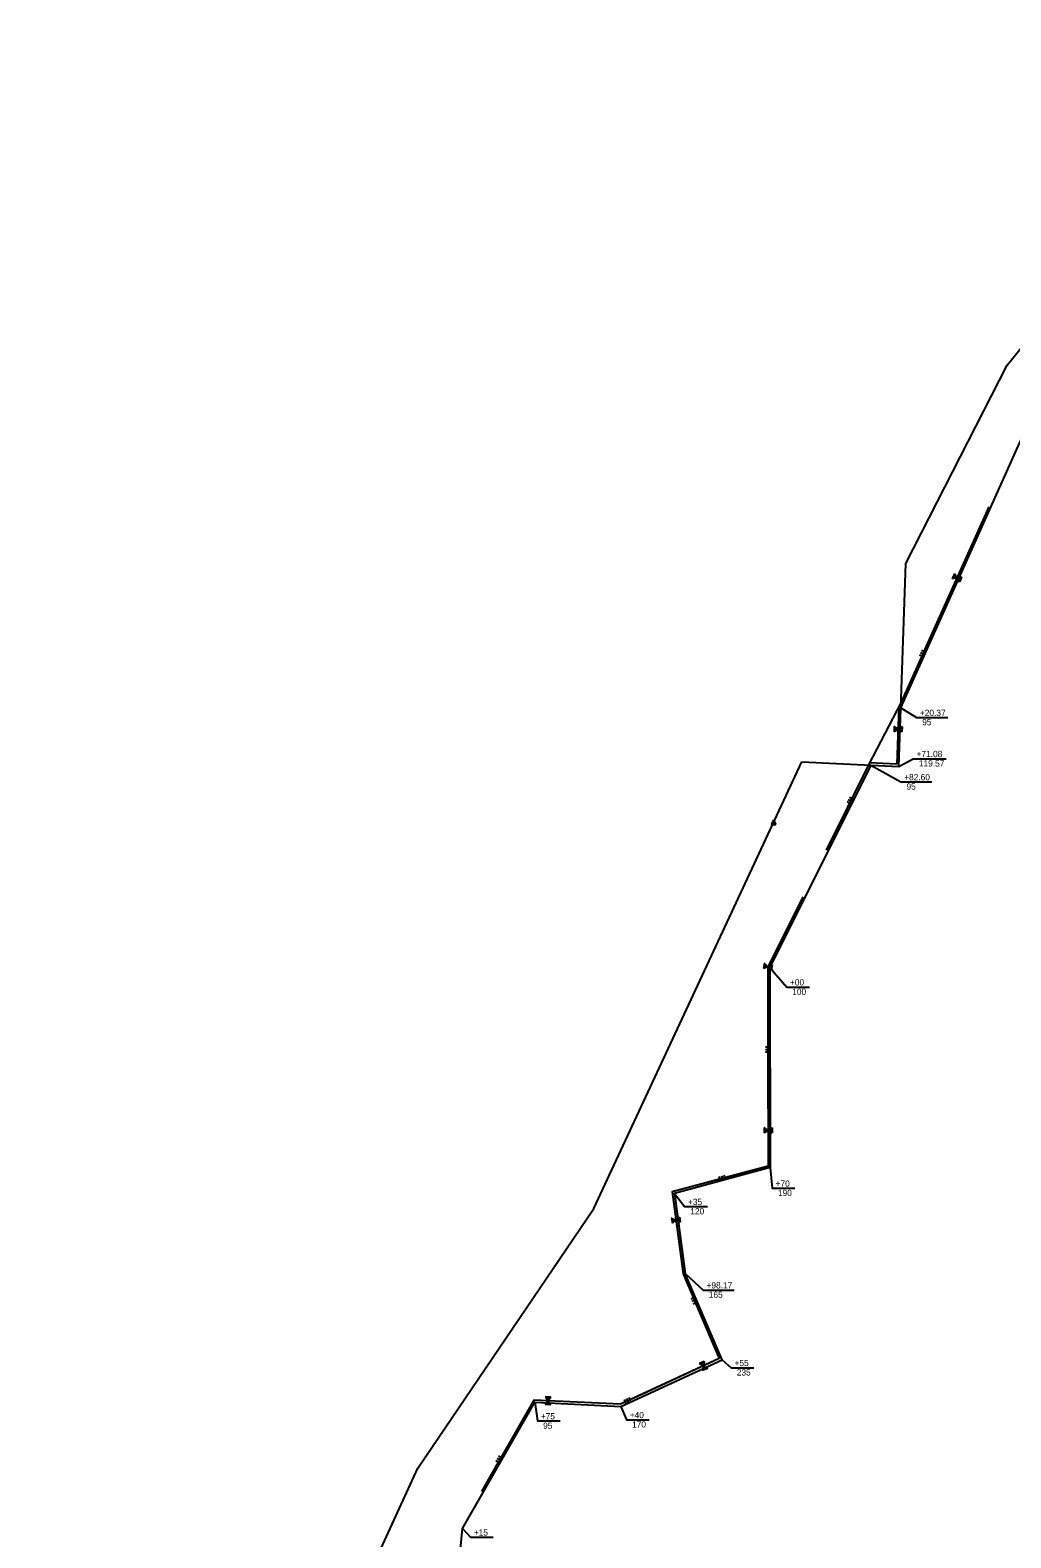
# Model space of a CAD drawing. Extents: x 979729 to 993523, y 1834148 to 1845433.
# Drawn here: x 980541 to 981483, y 1840365 to 1841814 of the extents above; entities that cross this region are included whole.
import ezdxf

# ---------------------------------------------------------------- set-up
doc = ezdxf.new("R2010")
doc.units = 0
for name, color, linetype in [('42', 7, 'Continuous'), ('51', 7, 'Continuous'), ('R_Draft', 7, 'Continuous'), ('S_EXIST_ROW', 7, 'Continuous')]:
    doc.layers.add(name, color=color, linetype=linetype)

msp = doc.modelspace()

# ---------------------------------------------------------------- linework, layer by layer
at = {"layer": '42'}
for p, q in [((981462.3, 1841356.2), (981377.9, 1841168.2)), ((981431.6, 1841287.8), (981427.1, 1841287)), ((981431.5, 1841287.9), (981427.2, 1841287.1)), ((981431.3, 1841288.1), (981427.3, 1841287.4)), ((981431.2, 1841288.3), (981427.4, 1841287.7)), ((981431.1, 1841288.5), (981427.6, 1841287.9)), ((981430.9, 1841288.8), (981427.7, 1841288.2)), ((981430.8, 1841289), (981427.8, 1841288.5)), ((981430.7, 1841289.2), (981427.9, 1841288.8)), ((981430.5, 1841289.5), (981428, 1841289)), ((981430.3, 1841289.7), (981428.2, 1841289.3)), ((981430.1, 1841290.1), (981428.4, 1841289.9)), ((981430, 1841290.4), (981428.5, 1841290.1)), ((981430.1, 1841289.9), (981428.5, 1841289.6)), ((981429.8, 1841290.6), (981428.7, 1841290.4)), ((981429.6, 1841290.8), (981428.8, 1841290.7)), ((981429.5, 1841291.1), (981428.9, 1841291)), ((981429.3, 1841291.3), (981429, 1841291.2)), ((981429.2, 1841291.6), (981431.6, 1841287.8)), ((981429.2, 1841291.5), (981429.2, 1841291.5)), ((981436, 1841288.5), (981431.6, 1841287.8)), ((981431.6, 1841287.8), (981434, 1841284)), ((981431.7, 1841287.8), (981434, 1841284.1)), ((981432, 1841287.8), (981434.2, 1841284.3)), ((981432.2, 1841287.9), (981434.3, 1841284.6)), ((981432.5, 1841287.9), (981434.4, 1841284.9)), ((981432.8, 1841288), (981434.5, 1841285.2)), ((981433.1, 1841288), (981434.6, 1841285.4)), ((981433.3, 1841288), (981434.8, 1841285.7)), ((981433.6, 1841288.1), (981434.9, 1841286)), ((981433.8, 1841288.1), (981435, 1841286.2)), ((981434.1, 1841288.1), (981435, 1841286.7)), ((981434.4, 1841288.2), (981435.3, 1841286.8)), ((981434.6, 1841288.3), (981435.4, 1841287.1)), ((981434.9, 1841288.3), (981435.5, 1841287.3)), ((981435.2, 1841288.3), (981435.6, 1841287.6)), ((981435.4, 1841288.4), (981435.8, 1841287.9)), ((981435.7, 1841288.4), (981435.9, 1841288.2)), ((981436, 1841288.5), (981436, 1841288.4)), ((981400.1, 1841211.5), (981395.5, 1841213.5)), ((981401.1, 1841213.8), (981396.6, 1841215.8)), ((981402.1, 1841216.1), (981397.6, 1841218.1)), ((981377.9, 1841168.2), (981346.6, 1841108)), ((981375, 1841142.3), (981371.2, 1841140)), ((981375.1, 1841142.3), (981371.2, 1841139.9)), ((981372.8, 1841143.9), (981371.3, 1841143)), ((981373.2, 1841143.6), (981371.3, 1841142.4)), ((981373.4, 1841143.4), (981371.3, 1841142.1)), ((981373.7, 1841143.3), (981371.3, 1841141.8)), ((981373.8, 1841143.1), (981371.3, 1841141.5)), ((981374.1, 1841143), (981371.3, 1841141.2)), ((981374.3, 1841142.8), (981371.3, 1841140.9)), ((981374.5, 1841142.7), (981371.3, 1841140.6)), ((981374.7, 1841142.5), (981371.3, 1841140.3)), ((981371.4, 1841144.9), (981375.1, 1841142.3)), ((981371.7, 1841144.7), (981371.4, 1841144.5)), ((981371.9, 1841144.6), (981371.4, 1841144.2)), ((981372.1, 1841144.4), (981371.4, 1841143.9)), ((981372.3, 1841144.2), (981371.4, 1841143.6)), ((981372.6, 1841144.1), (981371.4, 1841143.3)), ((981372.9, 1841143.7), (981371.5, 1841142.8)), ((981378.9, 1841144.7), (981375.1, 1841142.3)), ((981375.1, 1841142.3), (981378.7, 1841139.7)), ((981375.2, 1841142.3), (981378.7, 1841139.8)), ((981375.4, 1841142.5), (981378.7, 1841140.1)), ((981375.6, 1841142.6), (981378.8, 1841140.4)), ((981375.9, 1841142.8), (981378.8, 1841140.7)), ((981376.1, 1841142.9), (981378.8, 1841141)), ((981376.4, 1841143), (981378.8, 1841141.3)), ((981376.5, 1841143.2), (981378.8, 1841141.6)), ((981376.8, 1841143.3), (981378.8, 1841141.9)), ((981377, 1841143.5), (981378.8, 1841142.2)), ((981377.3, 1841143.6), (981378.7, 1841142.6)), ((981377.5, 1841143.8), (981378.8, 1841142.8)), ((981377.7, 1841143.9), (981378.8, 1841143.1)), ((981377.9, 1841144), (981378.9, 1841143.4)), ((981378.2, 1841144.2), (981378.9, 1841143.7)), ((981378.4, 1841144.3), (981378.9, 1841144)), ((981378.6, 1841144.5), (981378.9, 1841144.3)), ((981378.8, 1841144.6), (981378.9, 1841144.6)), ((981346.6, 1841108), (981305.8, 1841026.1)), ((981330.5, 1841070.1), (981326, 1841072.4)), ((981331.6, 1841072.4), (981327.2, 1841074.6)), ((981332.7, 1841074.6), (981328.3, 1841076.8)), ((981283.5, 1840981.3), (981249.9, 1840913.7)), ((981249.8, 1840914), (981245.7, 1840912.4)), ((981249.9, 1840913.9), (981245.7, 1840912.3)), ((981249.4, 1840914.4), (981245.8, 1840913)), ((981249.6, 1840914.1), (981245.8, 1840912.7)), ((981249.2, 1840914.5), (981245.9, 1840913.3)), ((981248.8, 1840914.9), (981246, 1840913.9)), ((981249.1, 1840914.8), (981246, 1840913.6)), ((981248.7, 1840915.1), (981246.1, 1840914.2)), ((981248.3, 1840915.5), (981246.2, 1840914.8)), ((981248.5, 1840915.3), (981246.2, 1840914.5)), ((981247.8, 1840916.1), (981246.4, 1840915.6)), ((981248, 1840915.9), (981246.4, 1840915.4)), ((981247.6, 1840916.3), (981246.5, 1840915.9)), ((981248.1, 1840915.7), (981246.5, 1840915.1)), ((981247.4, 1840916.5), (981246.6, 1840916.2)), ((981247, 1840916.9), (981246.7, 1840916.8)), ((981247.2, 1840916.7), (981246.7, 1840916.5)), ((981246.8, 1840917.2), (981249.9, 1840913.9)), ((981246.9, 1840917.1), (981246.8, 1840917.1)), ((981254.1, 1840915.5), (981249.9, 1840913.9)), ((981249.9, 1840913.9), (981253, 1840910.6)), ((981249.9, 1840913.7), (981250.2, 1840722.4)), ((981250, 1840913.9), (981253, 1840910.7)), ((981250.3, 1840914), (981253, 1840911)), ((981250.5, 1840914.1), (981253.1, 1840911.3)), ((981250.8, 1840914.2), (981253.2, 1840911.6)), ((981251, 1840914.3), (981253.3, 1840911.9)), ((981251.3, 1840914.3), (981253.3, 1840912.2)), ((981251.5, 1840914.5), (981253.4, 1840912.4)), ((981251.8, 1840914.5), (981253.5, 1840912.7)), ((981252, 1840914.6), (981253.5, 1840913)), ((981252.3, 1840914.7), (981253.5, 1840913.4)), ((981252.5, 1840914.9), (981253.7, 1840913.6)), ((981252.8, 1840915), (981253.7, 1840913.9)), ((981253, 1840915), (981253.8, 1840914.2)), ((981253.3, 1840915.1), (981253.9, 1840914.5)), ((981253.5, 1840915.2), (981254, 1840914.8)), ((981253.8, 1840915.3), (981254, 1840915.1)), ((981254, 1840915.4), (981254.1, 1840915.4)), ((981252.5, 1840836.7), (981247.5, 1840836.7)), ((981252.5, 1840834.2), (981247.5, 1840834.2)), ((981252.5, 1840831.7), (981247.5, 1840831.7)), ((981246.5, 1840759.2), (981246.4, 1840759.1)), ((981246.4, 1840759.2), (981250.2, 1840756.7)), ((981246.7, 1840759), (981246.4, 1840758.8)), ((981246.9, 1840758.9), (981246.4, 1840758.5)), ((981247.1, 1840758.7), (981246.4, 1840758.2)), ((981247.4, 1840758.6), (981246.4, 1840757.9)), ((981247.6, 1840758.4), (981246.4, 1840757.6)), ((981247.8, 1840758.3), (981246.4, 1840757.3)), ((981248.2, 1840758), (981246.4, 1840756.7)), ((981248.5, 1840757.8), (981246.4, 1840756.4)), ((981248.7, 1840757.7), (981246.4, 1840756.1)), ((981248.9, 1840757.5), (981246.4, 1840755.8)), ((981249.2, 1840757.4), (981246.4, 1840755.5)), ((981249.4, 1840757.2), (981246.4, 1840755.2)), ((981249.6, 1840757.1), (981246.4, 1840754.9)), ((981249.8, 1840756.9), (981246.4, 1840754.6)), ((981250.1, 1840756.8), (981246.4, 1840754.3)), ((981250.2, 1840756.7), (981246.4, 1840754.2)), ((981248, 1840758.1), (981246.6, 1840757.1)), ((981253.9, 1840759.2), (981250.2, 1840756.7)), ((981250.2, 1840756.7), (981253.9, 1840754.2)), ((981250.3, 1840756.8), (981253.9, 1840754.3)), ((981250.5, 1840756.9), (981253.9, 1840754.6)), ((981250.7, 1840757.1), (981253.9, 1840755)), ((981251, 1840757.2), (981253.9, 1840755.3)), ((981251.2, 1840757.4), (981253.9, 1840755.6)), ((981251.4, 1840757.5), (981253.9, 1840755.9)), ((981251.6, 1840757.7), (981253.9, 1840756.2)), ((981251.9, 1840757.8), (981253.9, 1840756.5)), ((981252.1, 1840758), (981253.9, 1840756.8)), ((981252.4, 1840758.1), (981253.8, 1840757.1)), ((981252.5, 1840758.3), (981253.9, 1840757.4)), ((981252.7, 1840758.4), (981253.9, 1840757.7)), ((981253, 1840758.6), (981253.9, 1840758)), ((981253.2, 1840758.7), (981253.9, 1840758.3)), ((981253.4, 1840758.9), (981253.9, 1840758.6)), ((981253.7, 1840759), (981253.9, 1840758.9)), ((981253.9, 1840759.2), (981253.9, 1840759.2)), ((981250.2, 1840722.4), (981157.8, 1840697.5)), ((981204.4, 1840707.5), (981203.1, 1840712.3)), ((981206.8, 1840708.1), (981205.5, 1840712.9)), ((981209.2, 1840708.8), (981207.9, 1840713.6)), ((981157.8, 1840697.5), (981168.4, 1840618.6)), ((981157.4, 1840672.3), (981161.5, 1840670.3)), ((981157.5, 1840672.2), (981157.4, 1840672.2)), ((981157.7, 1840672.1), (981157.5, 1840671.9)), ((981158, 1840672), (981157.5, 1840671.6)), ((981158.2, 1840671.9), (981157.5, 1840671.3)), ((981158.4, 1840671.7), (981157.6, 1840671)), ((981158.7, 1840671.6), (981157.6, 1840670.7)), ((981158.9, 1840671.5), (981157.7, 1840670.4)), ((981159.4, 1840671.3), (981157.7, 1840669.8)), ((981159.1, 1840671.3), (981157.8, 1840670.2)), ((981159.6, 1840671.1), (981157.8, 1840669.5)), ((981159.9, 1840671), (981157.8, 1840669.2)), ((981160.1, 1840670.9), (981157.9, 1840668.9)), ((981160.4, 1840670.8), (981157.9, 1840668.6)), ((981160.6, 1840670.7), (981157.9, 1840668.3)), ((981160.9, 1840670.6), (981158, 1840668)), ((981161.1, 1840670.4), (981158, 1840667.7)), ((981161.4, 1840670.3), (981158.1, 1840667.4)), ((981161.5, 1840670.3), (981158.1, 1840667.3)), ((981164.8, 1840673.3), (981161.5, 1840670.3)), ((981161.5, 1840670.3), (981165.5, 1840668.4)), ((981161.5, 1840670.3), (981165.5, 1840668.3)), ((981161.8, 1840670.5), (981165.5, 1840668.7)), ((981162, 1840670.7), (981165.4, 1840669)), ((981162.2, 1840670.9), (981165.4, 1840669.3)), ((981162.4, 1840671.1), (981165.3, 1840669.6)), ((981162.6, 1840671.2), (981165.3, 1840669.9)), ((981162.8, 1840671.4), (981165.3, 1840670.2)), ((981163, 1840671.6), (981165.2, 1840670.5)), ((981163.2, 1840671.8), (981165.2, 1840670.8)), ((981163.4, 1840671.9), (981165, 1840671.2)), ((981163.6, 1840672.1), (981165.1, 1840671.4)), ((981163.8, 1840672.3), (981165.1, 1840671.7)), ((981164, 1840672.5), (981165, 1840672)), ((981164.2, 1840672.7), (981165, 1840672.3)), ((981164.4, 1840672.9), (981164.9, 1840672.6)), ((981164.6, 1840673), (981164.9, 1840672.9)), ((981164.8, 1840673.2), (981164.9, 1840673.2)), ((981168.4, 1840618.6), (981203.2, 1840537.2)), ((981180.7, 1840596.3), (981176.1, 1840594.3)), ((981181.7, 1840594), (981177.1, 1840592)), ((981182.7, 1840591.7), (981178.1, 1840589.7)), ((981203.2, 1840537.2), (981108.3, 1840493.3)), ((981187.9, 1840530.2), (981184.1, 1840532.5)), ((981187.9, 1840530.3), (981184.2, 1840532.6)), ((981187.9, 1840530.6), (981184.4, 1840532.7)), ((981188, 1840530.8), (981184.7, 1840532.8)), ((981188, 1840531.1), (981185, 1840532.9)), ((981188.1, 1840531.3), (981185.3, 1840533.1)), ((981188.1, 1840531.6), (981185.5, 1840533.2)), ((981188.2, 1840531.9), (981185.8, 1840533.3)), ((981188.2, 1840532.2), (981186.1, 1840533.4)), ((981188.2, 1840532.4), (981186.4, 1840533.6)), ((981188.2, 1840532.7), (981186.8, 1840533.6)), ((981188.3, 1840532.9), (981186.9, 1840533.8)), ((981188.4, 1840533.2), (981187.2, 1840533.9)), ((981187.9, 1840530.2), (981187.2, 1840525.7)), ((981188, 1840530.1), (981187.3, 1840525.8)), ((981188.4, 1840533.5), (981187.4, 1840534.1)), ((981188.2, 1840529.9), (981187.6, 1840525.9)), ((981188.5, 1840533.8), (981187.7, 1840534.2)), ((981188.6, 1840534.6), (981187.9, 1840530.2)), ((981191.8, 1840527.8), (981187.9, 1840530.2)), ((981188.5, 1840529.8), (981187.9, 1840526)), ((981188.5, 1840534), (981188, 1840534.3)), ((981188.7, 1840529.7), (981188.1, 1840526.1)), ((981188.5, 1840534.3), (981188.3, 1840534.5)), ((981188.9, 1840529.5), (981188.4, 1840526.3)), ((981188.6, 1840534.5), (981188.5, 1840534.6)), ((981189.1, 1840529.3), (981188.7, 1840526.4)), ((981189.4, 1840529.2), (981189, 1840526.5)), ((981189.6, 1840529.1), (981189.2, 1840526.6)), ((981189.8, 1840528.9), (981189.5, 1840526.8)), ((981190.1, 1840528.7), (981189.8, 1840527.1)), ((981190.3, 1840528.7), (981190.1, 1840527)), ((981190.5, 1840528.6), (981190.3, 1840527.1)), ((981190.8, 1840528.4), (981190.6, 1840527.3)), ((981191, 1840528.2), (981190.9, 1840527.4)), ((981191.2, 1840528.1), (981191.1, 1840527.5)), ((981191.5, 1840528), (981191.4, 1840527.6)), ((981191.7, 1840527.8), (981191.7, 1840527.8)), ((981038.6, 1840496.7), (981036.3, 1840500.6)), ((981038.7, 1840496.8), (981036.4, 1840500.6)), ((981038.8, 1840497.1), (981036.7, 1840500.6)), ((981039, 1840497.2), (981037, 1840500.5)), ((981039.1, 1840497.5), (981037.3, 1840500.5)), ((981039.3, 1840497.7), (981037.6, 1840500.5)), ((981039.4, 1840497.9), (981037.9, 1840500.5)), ((981039.6, 1840498.1), (981038.2, 1840500.5)), ((981039.8, 1840498.4), (981038.5, 1840500.5)), ((981041.3, 1840500.3), (981038.6, 1840496.7)), ((981039.9, 1840498.6), (981038.8, 1840500.5)), ((981040.1, 1840498.8), (981039.2, 1840500.3)), ((981040.3, 1840499), (981039.4, 1840500.4)), ((981040.4, 1840499.2), (981039.7, 1840500.4)), ((981040.6, 1840499.4), (981040, 1840500.4)), ((981040.7, 1840499.7), (981040.3, 1840500.4)), ((981040.9, 1840499.9), (981040.6, 1840500.4)), ((981041.1, 1840500.1), (981040.9, 1840500.4)), ((981041.2, 1840500.3), (981041.2, 1840500.3)), ((981024.9, 1840497.4), (980974.5, 1840409.4)), ((981108.3, 1840493.3), (981024.9, 1840497.4)), ((981038.6, 1840496.7), (981035.9, 1840493.1)), ((981038.6, 1840496.6), (981036, 1840493.1)), ((981038.8, 1840496.4), (981036.3, 1840493.1)), ((981038.9, 1840496.2), (981036.6, 1840493.1)), ((981039, 1840495.9), (981036.9, 1840493)), ((981039.2, 1840495.7), (981037.2, 1840493)), ((981039.3, 1840495.4), (981037.5, 1840493)), ((981039.5, 1840495.2), (981037.8, 1840493)), ((981039.6, 1840495), (981038.1, 1840493)), ((981039.7, 1840494.7), (981038.4, 1840493)), ((981040.9, 1840492.8), (981038.6, 1840496.7)), ((981039.8, 1840494.5), (981038.8, 1840493.1)), ((981040, 1840494.3), (981039, 1840492.9)), ((981040.2, 1840494.1), (981039.3, 1840492.9)), ((981040.3, 1840493.8), (981039.6, 1840492.9)), ((981040.4, 1840493.6), (981039.9, 1840492.9)), ((981040.6, 1840493.4), (981040.2, 1840492.9)), ((981040.7, 1840493.1), (981040.5, 1840492.9)), ((981040.9, 1840492.9), (981040.8, 1840492.9)), ((981114.1, 1840493.3), (981112, 1840497.8)), ((981116.4, 1840494.3), (981114.3, 1840498.9)), ((981118.6, 1840495.4), (981116.5, 1840499.9)), ((980995.3, 1840440.8), (980991, 1840443.3)), ((980992.9, 1840436.5), (980988.5, 1840439)), ((980994.1, 1840438.6), (980989.8, 1840441.1))]:
    msp.add_line(p, q, dxfattribs=at)
for points in [[(981462.3, 1841356.2), (981400.9, 1841219.4)], [(981429.2, 1841291.6), (981427.1, 1841287)], [(981436, 1841288.5), (981434, 1841284)], [(981397.8, 1841212.5), (981375.8, 1841163.4)], [(981375.8, 1841163.4), (981373.9, 1841108.7)], [(981371.4, 1841144.9), (981371.2, 1841139.9)], [(981378.9, 1841144.7), (981378.7, 1841139.7)], [(981347.6, 1841110), (981346.6, 1841108), (981331.6, 1841078)], [(981373.9, 1841108.7), (981347.6, 1841110)], [(981328.3, 1841071.2), (981305.8, 1841026.1)], [(981283.5, 1840981.3), (981249.9, 1840913.7), (981250, 1840839.2)], [(981246.8, 1840917.2), (981245.7, 1840912.3)], [(981254.1, 1840915.5), (981253, 1840910.6)], [(981250, 1840831.7), (981250.2, 1840722.4), (981211, 1840711.8)], [(981246.4, 1840759.2), (981246.4, 1840754.2)], [(981253.9, 1840759.2), (981253.9, 1840754.2)], [(981203.7, 1840709.9), (981157.8, 1840697.5), (981168.4, 1840618.6), (981177.4, 1840597.6)], [(981157.4, 1840672.3), (981158.1, 1840667.3)], [(981164.8, 1840673.3), (981165.5, 1840668.3)], [(981180.4, 1840590.7), (981203.2, 1840537.2), (981119.9, 1840498.7)], [(981188.6, 1840534.6), (981184.1, 1840532.5)], [(981191.8, 1840527.8), (981187.2, 1840525.7)], [(981041.3, 1840500.3), (981036.3, 1840500.6)], [(981113, 1840495.5), (981108.3, 1840493.3), (981024.9, 1840497.4), (980994.4, 1840444.2)], [(981040.9, 1840492.8), (981035.9, 1840493.1)], [(980990.7, 1840437.7), (980974.5, 1840409.4)]]:
    msp.add_lwpolyline(points, dxfattribs=at)
at = {"layer": '51'}
for points in [[(981377.8, 1841163), (981546.7, 1841539.4), (981629.8, 1841630.1), (981776.3, 1841623), (982137.6, 1841744.5), (982163.1, 1841753.1)], [(981348.8, 1841107.9), (981251.9, 1840913.2), (981252.2, 1840720.9), (981160, 1840696), (981170.4, 1840619.1)], [(980949.9, 1840308), (980956.3, 1840373.8), (981026, 1840495.3), (981108.7, 1840491.3), (981205.8, 1840536.2), (981170.4, 1840619.1)]]:
    msp.add_lwpolyline(points, dxfattribs=at)
at = {"layer": 'R_Draft'}
for p, q in [((981398.9, 1841153.6), (981422.8, 1841153.6)), ((981395.6, 1841114), (981421.3, 1841114)), ((981383.7, 1841091.7), (981407.6, 1841091.7)), ((981274, 1840894.5), (981289.8, 1840894.5)), ((981260.1, 1840701), (981275.9, 1840701)), ((981175.9, 1840683.4), (981191.7, 1840683.4)), ((981193.7, 1840603.2), (981217.6, 1840603.2)), ((981220.6, 1840528.5), (981236.4, 1840528.5)), ((981034.4, 1840477.3), (981050.2, 1840477.3)), ((981119.9, 1840478.5), (981135.7, 1840478.5)), ((980970, 1840365.6), (980985.8, 1840365.6))]:
    msp.add_line(p, q, dxfattribs=at)
for points in [[(981377.8, 1841163), (981392.9, 1841153.6), (981398.9, 1841153.6)], [(981375.9, 1841106.6), (981389.6, 1841114), (981395.6, 1841114)], [(981348.8, 1841107.9), (981377.7, 1841091.7), (981383.7, 1841091.7)], [(981251.9, 1840913.2), (981268, 1840894.5), (981274, 1840894.5)], [(981252.2, 1840720.9), (981254.1, 1840701), (981260.1, 1840701)], [(981160, 1840696), (981169.9, 1840683.4), (981175.9, 1840683.4)], [(981170.4, 1840619.1), (981187.7, 1840603.2), (981193.7, 1840603.2)], [(981205.8, 1840536.2), (981214.6, 1840528.5), (981220.6, 1840528.5)], [(981026, 1840495.3), (981028.4, 1840477.3), (981034.4, 1840477.3)], [(981108.7, 1840491.3), (981113.9, 1840478.5), (981119.9, 1840478.5)], [(980956.3, 1840373.8), (980964, 1840365.6), (980970, 1840365.6)]]:
    msp.add_lwpolyline(points, dxfattribs=at)
at = {"layer": 'S_EXIST_ROW'}
for p, q in [((981479.9, 1841492.3), (981738.4, 1841814.4)), ((981382.5, 1841301.8), (981479.9, 1841492.3)), ((981375.9, 1841106.6), (981382.5, 1841301.8)), ((981082.5, 1840681.4), (981282.4, 1841111)), ((981282.4, 1841111), (981375.9, 1841106.6)), ((981255.4, 1841055.1), (981253.1, 1841050.6)), ((981255.3, 1841052.1), (981255.3, 1841052.1)), ((981255.4, 1841055.1), (981257.6, 1841050.6)), ((981253.1, 1841050.6), (981257.6, 1841050.6)), ((980913.4, 1840432), (981082.5, 1840681.4)), ((980540.8, 1839619.6), (980913.4, 1840432))]:
    msp.add_line(p, q, dxfattribs=at)
for radius in [0.0768, 0.0384]:
    msp.add_circle((981255.3, 1841052.1), radius, dxfattribs=at)

# ---------------------------------------------------------------- texts
at = {"layer": 'R_Draft'}
for s, p in [('+20.37', (981396, 1841155.1)), (' 95', (981396, 1841146.1)), ('+71.08', (981392.8, 1841115.5)), (' 119.57', (981392.8, 1841106.5)), ('+82.60', (981380.9, 1841093.2)), (' 95', (981380.9, 1841084.2)), ('+00', (981271.1, 1840896)), (' 100', (981271.1, 1840887)), ('+70', (981257.3, 1840702.5)), ('+35', (981173.1, 1840684.9)), (' 190', (981257.3, 1840693.5)), (' 120', (981173.1, 1840675.9)), ('+98.17', (981190.9, 1840604.7)), (' 165', (981190.9, 1840595.7)), ('+55', (981217.8, 1840530)), (' 235', (981217.8, 1840521)), ('+40', (981117.1, 1840480)), ('+75', (981031.6, 1840478.8)), (' 95', (981031.6, 1840469.8)), (' 170', (981117.1, 1840471)), ('+15', (980967.2, 1840367.1))]:
    msp.add_text(s, height=6, rotation=360, dxfattribs=at).set_placement(p)

doc.saveas('drawing.dxf')
